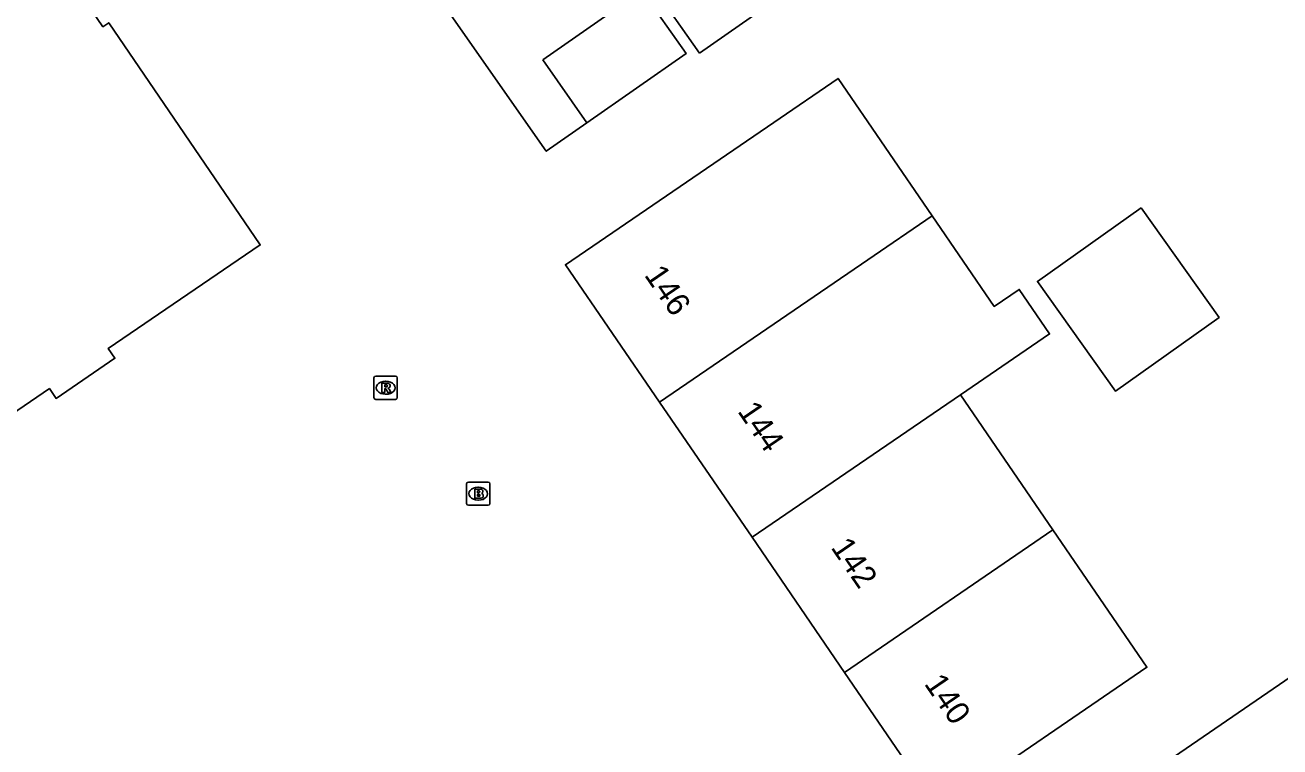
# Model space of a CAD drawing. Extents: x 157466 to 158888, y 383063 to 384677.
# Drawn here: x 158069.4 to 158123.3, y 383338.8 to 383369.8 of the extents above; entities that cross this region are included whole.
import ezdxf

# ---------------------------------------------------------------- set-up
doc = ezdxf.new("R2010")
doc.units = 0
for name, color, linetype in [('IMGEO_Brandkraan', 7, 'Continuous'), ('IMGEO_Pand', 7, 'Continuous'), ('IMGEO_Pand_nummerreeks', 7, 'Continuous'), ('IMGEO_Pand_vergunning_verleend', 7, 'Continuous'), ('IMGEO_Rioolput', 7, 'Continuous'), ('IMGEO_Voetpad_open', 7, 'Continuous')]:
    doc.layers.add(name, color=color, linetype=linetype)

msp = doc.modelspace()

# ---------------------------------------------------------------- linework, layer by layer
at = {"layer": 'IMGEO_Brandkraan'}
for p, q in [((158088.355, 383349.259), (158088.355, 383350.111)), ((158088.43, 383350.185), (158089.282, 383350.185)), ((158088.843, 383349.965), (158088.868, 383349.965)), ((158089.356, 383350.111), (158089.356, 383349.259)), ((158088.866, 383349.405), (158088.841, 383349.405)), ((158089.282, 383349.185), (158088.43, 383349.185))]:
    msp.add_line(p, q, dxfattribs=at)
for points in [[(158088.355, 383349.259), (158088.355, 383350.111)], [(158088.43, 383350.185), (158089.282, 383350.185)], [(158088.703, 383349.885), (158088.703, 383349.485), (158088.916, 383349.485)], [(158088.934, 383349.885), (158088.703, 383349.885)], [(158088.882, 383349.804), (158088.828, 383349.804), (158088.828, 383349.728)], [(158089.356, 383350.111), (158089.356, 383349.259)], [(158088.828, 383349.728), (158088.881, 383349.728)], [(158088.89, 383349.652), (158088.828, 383349.652), (158088.828, 383349.571)], [(158088.828, 383349.571), (158088.89, 383349.571)], [(158089.282, 383349.185), (158088.43, 383349.185)]]:
    msp.add_lwpolyline(points, dxfattribs=at)
for centre, radius, start, end in [((158088.432, 383350.109), 0.0765, 91.552, 178.448), ((158088.432, 383350.109), 0.0765, 91.552, 178.448), ((158088.883, 383349.766), 0.0379, 267.8285, 90.9355), ((158088.938, 383349.74), 0.145, 59.4692, 91.5367), ((158088.963, 383349.787), 0.0922, 285.5137, 58.1501), ((158089.28, 383350.109), 0.0765, 1.552, 88.448), ((158089.28, 383350.109), 0.0765, 1.552, 88.448), ((158088.432, 383349.261), 0.0765, 181.552, 268.448), ((158088.432, 383349.261), 0.0765, 181.552, 268.448), ((158088.891, 383349.611), 0.0404, 269.8759, 90.5077), ((158088.922, 383349.736), 0.251, 268.6676, 293.5347), ((158088.968, 383349.595), 0.105, 301.3115, 78.989), ((158089.28, 383349.261), 0.0765, 271.552, 358.448), ((158089.28, 383349.261), 0.0765, 271.552, 358.448)]:
    msp.add_arc(centre, radius, start, end, dxfattribs=at)
for centre, major_axis, ratio, start_param, end_param in [((158088.842, 383349.685), (-0.387, 0.002), 0.722429, 4.712389, 7.853982), ((158088.867, 383349.685), (-0.39, 0.002), 0.717154, 1.570796, 4.712389)]:
    msp.add_ellipse(centre, major_axis=major_axis, ratio=ratio, start_param=start_param, end_param=end_param, dxfattribs=at)
at = {"layer": 'IMGEO_Pand'}
for points in [[(158098.346, 383368.602), (158096.273, 383371.568), (158101.387, 383375.142), (158103.459, 383372.177), (158098.346, 383368.602)], [(158063.457, 383349.42), (158070.453, 383354.196), (158070.741, 383353.776), (158073.267, 383355.504), (158072.98, 383355.926), (158079.5, 383360.371), (158073, 383369.907), (158072.752, 383369.739), (158070.217, 383373.469), (158065.818, 383370.478), (158066.004, 383370.206), (158059.232, 383365.6), (158059.047, 383365.873), (158054.649, 383362.864), (158057.202, 383359.135), (158056.946, 383358.96), (158063.457, 383349.42)], [(158091.622, 383368.318), (158093.517, 383365.607), (158097.773, 383368.581), (158095.878, 383371.292), (158091.622, 383368.318)], [(158108.334, 383361.618), (158104.298, 383367.518), (158101.538, 383365.63), (158092.598, 383359.514), (158096.635, 383353.614)], [(158117.298, 383361.964), (158112.844, 383358.799), (158116.191, 383354.09), (158120.645, 383357.256), (158117.298, 383361.964)], [(158096.635, 383353.614), (158105.574, 383359.73), (158108.334, 383361.618)], [(158108.334, 383361.618), (158110.995, 383357.728), (158112.065, 383358.46), (158113.372, 383356.549), (158109.543, 383353.93)], [(158100.603, 383347.814), (158096.635, 383353.614)], [(158109.543, 383353.93), (158100.603, 383347.814)], [(158113.511, 383348.129), (158109.543, 383353.93)], [(158100.603, 383347.814), (158104.572, 383342.012)], [(158104.572, 383342.012), (158113.511, 383348.129)], [(158113.511, 383348.129), (158117.548, 383342.229), (158108.608, 383336.113), (158104.572, 383342.012)]]:
    msp.add_lwpolyline(points, dxfattribs=at)
at = {"layer": 'IMGEO_Pand_vergunning_verleend'}
msp.add_lwpolyline([(158087.291, 383370.796), (158093.292, 383374.991), (158095.878, 383371.292), (158097.773, 383368.581), (158093.517, 383365.607), (158091.771, 383364.387), (158087.291, 383370.796)], dxfattribs=at)
at = {"layer": 'IMGEO_Rioolput'}
for p, q in [((158084.381, 383353.809), (158084.381, 383354.661)), ((158084.456, 383354.735), (158085.308, 383354.735)), ((158085.382, 383354.661), (158085.382, 383353.809)), ((158084.869, 383354.515), (158084.894, 383354.515)), ((158085.308, 383353.735), (158084.456, 383353.735)), ((158084.892, 383353.955), (158084.867, 383353.955))]:
    msp.add_line(p, q, dxfattribs=at)
for points in [[(158084.381, 383353.809), (158084.381, 383354.661)], [(158084.456, 383354.735), (158085.308, 383354.735)], [(158085.382, 383354.661), (158085.382, 383353.809)], [(158084.97, 383354.433), (158084.718, 383354.435), (158084.718, 383354.035)], [(158084.718, 383354.035), (158084.842, 383354.035), (158084.842, 383354.197), (158084.853, 383354.197)], [(158084.896, 383354.354), (158084.842, 383354.354), (158084.842, 383354.273)], [(158084.842, 383354.273), (158084.894, 383354.273)], [(158084.9, 383354.168), (158084.971, 383354.035), (158085.111, 383354.035), (158085.046, 383354.161)], [(158085.308, 383353.735), (158084.456, 383353.735)]]:
    msp.add_lwpolyline(points, dxfattribs=at)
for centre, radius, start, end in [((158084.458, 383354.659), 0.0765, 91.552, 178.448), ((158084.458, 383354.659), 0.0765, 91.552, 178.448), ((158085.306, 383354.659), 0.0765, 1.552, 88.448), ((158085.306, 383354.659), 0.0765, 1.552, 88.448), ((158084.852, 383354.144), 0.0533, 26.0293, 88.6989), ((158084.878, 383354.462), 0.19, 274.7715, 282.9687), ((158084.902, 383354.258), 0.0964, 77.0061, 93.1865), ((158084.916, 383354.315), 0.0378, 276.6634, 79.6772), ((158084.969, 383354.323), 0.109, 350.3612, 89.416), ((158084.967, 383354.323), 0.112, 277.5842, 350.9817), ((158084.951, 383354.108), 0.108, 29.5134, 73.7905), ((158084.458, 383353.811), 0.0765, 181.552, 268.448), ((158084.458, 383353.811), 0.0765, 181.552, 268.448), ((158085.306, 383353.811), 0.0765, 271.552, 358.448), ((158085.306, 383353.811), 0.0765, 271.552, 358.448)]:
    msp.add_arc(centre, radius, start, end, dxfattribs=at)
for centre, major_axis, ratio, start_param, end_param in [((158084.868, 383354.235), (-0.387, 0.002), 0.722429, 4.712389, 7.853982), ((158084.893, 383354.235), (-0.39, 0.002), 0.717154, 1.570796, 4.712389)]:
    msp.add_ellipse(centre, major_axis=major_axis, ratio=ratio, start_param=start_param, end_param=end_param, dxfattribs=at)
at = {"layer": 'IMGEO_Voetpad_open'}
msp.add_lwpolyline([(158164.625, 383369.809), (158164.424, 383369.653), (158139.528, 383352.671), (158091.649, 383319.824)], dxfattribs=at)

# ---------------------------------------------------------------- texts
at = {"layer": 'IMGEO_Pand_nummerreeks'}
for s, rotation, p in [('146', 304.3773, (158095.952, 383359.074)), ('144', 304.3773, (158099.954, 383353.224)), ('142', 304.3783, (158103.956, 383347.376)), ('140', 304.3783, (158107.962, 383341.521))]:
    msp.add_text(s, height=1, rotation=rotation, dxfattribs=at).set_placement(p)

doc.saveas('drawing.dxf')
